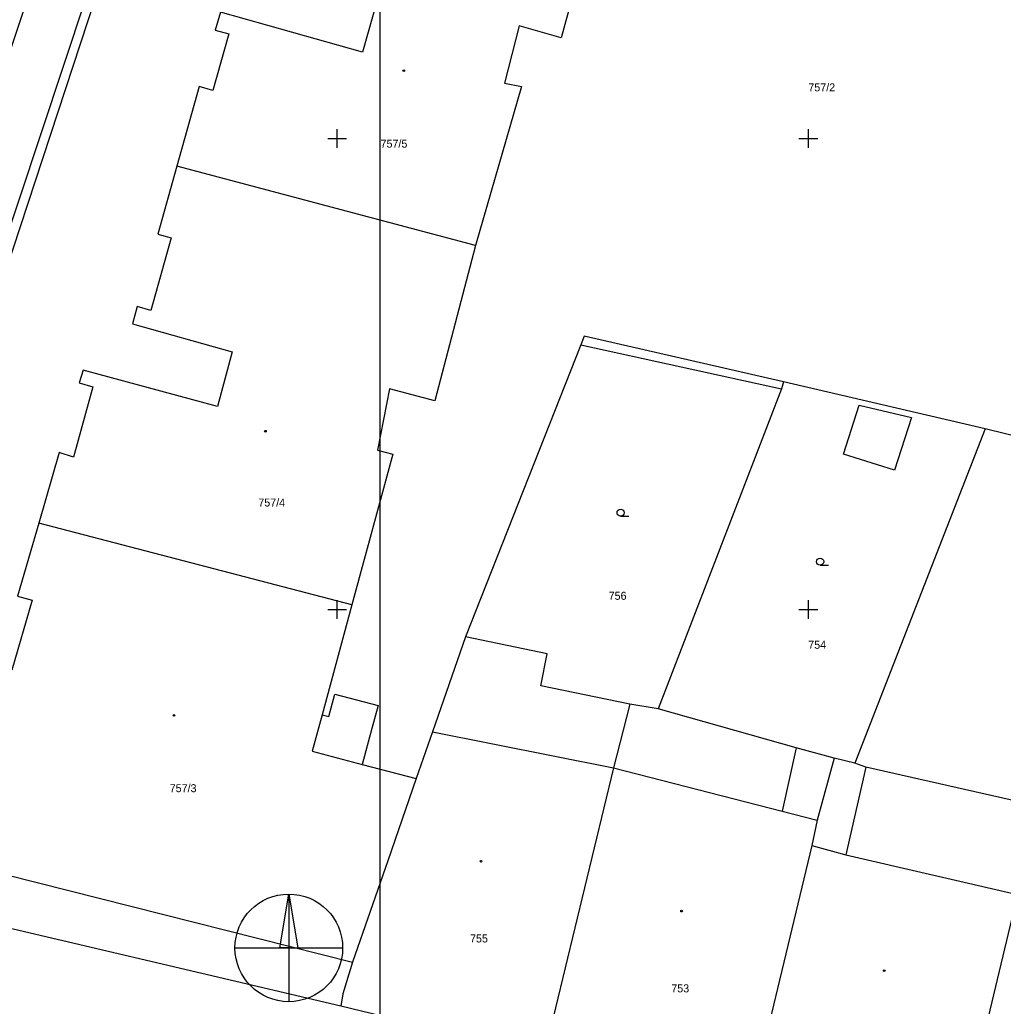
# Model space of a CAD drawing. Extents: x -599717 to -599336, y -1161826 to -1161587.
# Drawn here: x -599473.47 to -599431.73, y -1161736.85 to -1161694.96 of the extents above; entities that cross this region are included whole.
import ezdxf

# ---------------------------------------------------------------- set-up
doc = ezdxf.new("R2010")
doc.units = 0
for name, color, linetype in [('KN_Hranice parcel', 7, 'Continuous'), ('KN_Parcelní čísla', 7, 'Continuous'), ('KN_Vnitřní kresba', 7, 'Continuous'), ('KN_Značky budov', 7, 'Continuous'), ('KN_Značky kultur', 7, 'Continuous'), ('Vrstva 56', 7, 'Continuous'), ('X_RAM_ROZPISKA', 7, 'Continuous'), ('X_SOUR_KRIZKY_SEVER', 7, 'Continuous')]:
    doc.layers.add(name, color=color, linetype=linetype)

msp = doc.modelspace()

# ---------------------------------------------------------------- linework, layer by layer
at = {"layer": 'KN_Hranice parcel'}
for p, q in [((-599454.12, -1161704.55), (-599466.8, -1161701.17)), ((-599432.49, -1161712.33), (-599441.05, -1161710.34)), ((-599432.49, -1161712.33), (-599438.03, -1161726.53)), ((-599424.27, -1161714.38), (-599432.49, -1161712.33)), ((-599459.38, -1161719.8), (-599472.66, -1161716.33)), ((-599446.37, -1161724.22), (-599447.58, -1161724.02)), ((-599438.03, -1161726.53), (-599438.91, -1161726.32))]:
    msp.add_line(p, q, dxfattribs=at)
for points in [[(-599482.07, -1161728.43), (-599482.2, -1161727.17), (-599480.67, -1161718.88), (-599478.61, -1161710.51), (-599472.1, -1161690.95), (-599466.87, -1161675.9), (-599461.06, -1161668.48), (-599459.51, -1161667.19)], [(-599482.07, -1161728.43), (-599464.01, -1161674), (-599459.51, -1161667.19)], [(-599459.91, -1161683.02), (-599460.52, -1161682.87), (-599462.22, -1161689.15), (-599461.64, -1161689.31), (-599462.42, -1161692.2), (-599463, -1161692.05), (-599463.16, -1161692.62), (-599458.26, -1161693.97), (-599458.92, -1161696.33), (-599464.95, -1161694.63), (-599465.17, -1161695.4), (-599464.59, -1161695.56), (-599465.27, -1161697.96), (-599465.85, -1161697.8), (-599466.8, -1161701.17)], [(-599447.89, -1161686.25), (-599450.49, -1161695.73), (-599452.27, -1161695.22), (-599452.89, -1161697.65), (-599452.18, -1161697.79), (-599454.12, -1161704.55)], [(-599466.8, -1161701.17), (-599467.61, -1161704.06), (-599467.04, -1161704.22), (-599467.91, -1161707.3), (-599468.48, -1161707.14), (-599468.69, -1161707.87), (-599464.45, -1161709.06), (-599465.07, -1161711.38), (-599470.78, -1161709.84), (-599470.94, -1161710.37), (-599470.36, -1161710.54), (-599471.19, -1161713.54), (-599471.8, -1161713.33), (-599472.66, -1161716.33)], [(-599454.12, -1161704.55), (-599455.85, -1161711.14), (-599457.78, -1161710.63), (-599458.29, -1161713.23), (-599457.64, -1161713.4), (-599459.38, -1161719.8)], [(-599441.05, -1161710.34), (-599449.52, -1161708.39), (-599449.65, -1161708.76), (-599454.55, -1161721.16)], [(-599441.05, -1161710.34), (-599441.14, -1161710.63), (-599446.37, -1161724.22)], [(-599472.66, -1161716.33), (-599473.56, -1161719.43), (-599472.94, -1161719.61), (-599473.81, -1161722.58), (-599474.42, -1161722.4), (-599475.95, -1161727.69), (-599475.36, -1161727.86), (-599476.06, -1161730.26), (-599476.64, -1161730.09), (-599476.78, -1161730.57), (-599459.34, -1161734.98)], [(-599459.38, -1161719.8), (-599460.64, -1161724.48), (-599460.35, -1161724.55), (-599460.09, -1161723.59), (-599458.26, -1161724.08), (-599458.52, -1161725.05), (-599458.94, -1161726.58), (-599456.64, -1161727.18)], [(-599454.55, -1161721.16), (-599455.95, -1161725.2), (-599456.64, -1161727.18)], [(-599447.58, -1161724.02), (-599451.35, -1161723.24), (-599451.09, -1161721.88), (-599454.55, -1161721.16)], [(-599447.58, -1161724.02), (-599448.27, -1161726.72), (-599451.14, -1161738.62)], [(-599438.91, -1161726.32), (-599440.52, -1161725.88), (-599446.37, -1161724.22)], [(-599438.91, -1161726.32), (-599439.63, -1161728.95), (-599439.85, -1161730.03), (-599442.5, -1161741.05)], [(-599430.24, -1161728.35), (-599437.56, -1161726.69), (-599438.03, -1161726.53)], [(-599456.64, -1161727.18), (-599457.84, -1161730.67), (-599459.34, -1161734.98)], [(-599430.24, -1161728.35), (-599430.89, -1161731.22), (-599431.13, -1161732.11), (-599433.7, -1161742.87)], [(-599459.84, -1161736.84), (-599477.56, -1161732.68), (-599481.73, -1161731.59), (-599483.05, -1161731.39)], [(-599459.34, -1161734.98), (-599459.75, -1161736.32), (-599459.84, -1161736.84)], [(-599451.14, -1161738.62), (-599456.68, -1161737.34), (-599456.75, -1161737.6), (-599459.84, -1161736.84)]]:
    msp.add_lwpolyline(points, dxfattribs=at)
at = {"layer": 'KN_Vnitřní kresba'}
for p, q in [((-599464.97, -1161677.92), (-599478.91, -1161720.35)), ((-599449.65, -1161708.76), (-599441.14, -1161710.63)), ((-599438.51, -1161713.41), (-599437.84, -1161711.32)), ((-599437.84, -1161711.32), (-599435.62, -1161711.85)), ((-599435.62, -1161711.85), (-599436.35, -1161714.09)), ((-599436.35, -1161714.09), (-599438.51, -1161713.41)), ((-599460.64, -1161724.48), (-599461.06, -1161726.02)), ((-599455.95, -1161725.2), (-599448.27, -1161726.72)), ((-599461.06, -1161726.02), (-599458.94, -1161726.58)), ((-599440.52, -1161725.88), (-599441.11, -1161728.57)), ((-599448.27, -1161726.72), (-599441.11, -1161728.57)), ((-599437.56, -1161726.69), (-599438.41, -1161730.42)), ((-599441.11, -1161728.57), (-599439.63, -1161728.95)), ((-599439.85, -1161730.03), (-599438.41, -1161730.42)), ((-599438.41, -1161730.42), (-599431.13, -1161732.11))]:
    msp.add_line(p, q, dxfattribs=at)
at = {"layer": 'KN_Značky budov'}
for centre in [(-599457.171, -1161697.12), (-599463.041, -1161712.43), (-599466.921, -1161724.5), (-599453.891, -1161730.69), (-599445.381, -1161732.81), (-599436.781, -1161735.34)]:
    msp.add_circle(centre, 0.035, dxfattribs=at)
at = {"layer": 'KN_Značky kultur'}
for p, q in [((-599447.969, -1161716.04), (-599447.619, -1161716.04)), ((-599439.499, -1161718.12), (-599439.149, -1161718.12))]:
    msp.add_line(p, q, dxfattribs=at)
for centre in [(-599447.969, -1161715.89), (-599439.499, -1161717.97)]:
    msp.add_circle(centre, 0.15, dxfattribs=at)
at = {"layer": 'Vrstva 56'}
for p, q in [((-599462.05, -1161732.086), (-599461.669, -1161734.371)), ((-599464.335, -1161734.371), (-599459.765, -1161734.371)), ((-599462.05, -1161734.371), (-599462.05, -1161736.656))]:
    msp.add_line(p, q, dxfattribs=at)
msp.add_lwpolyline([(-599462.05, -1161732.086), (-599462.05, -1161734.371), (-599462.431, -1161734.371)], close=True, dxfattribs=at)
msp.add_circle((-599462.05, -1161734.371), 2.285, dxfattribs=at)
at = {"layer": 'X_RAM_ROZPISKA'}
msp.add_lwpolyline([(-599584.175, -1161747.535), (-599458.175, -1161747.535), (-599458.175, -1161628.735), (-599584.175, -1161628.735)], close=True, dxfattribs=at)
at = {"layer": 'X_SOUR_KRIZKY_SEVER'}
for p, q in [((-599460, -1161700.4), (-599460, -1161699.6)), ((-599440, -1161700.4), (-599440, -1161699.6)), ((-599460.4, -1161700), (-599459.6, -1161700)), ((-599440.4, -1161700), (-599439.6, -1161700)), ((-599460, -1161720.4), (-599460, -1161719.6)), ((-599440, -1161720.4), (-599440, -1161719.6)), ((-599460.4, -1161720), (-599459.6, -1161720)), ((-599440.4, -1161720), (-599439.6, -1161720))]:
    msp.add_line(p, q, dxfattribs=at)

# ---------------------------------------------------------------- texts
at = {"layer": 'KN_Parcelní čísla'}
for s, p in [('757/2', (-599440, -1161698)), ('757/5', (-599458.156, -1161700.39)), ('757/4', (-599463.343, -1161715.63)), ('756', (-599448.475, -1161719.59)), ('754', (-599440.005, -1161721.67)), ('757/3', (-599467.104, -1161727.76)), ('755', (-599454.358, -1161734.14)), ('753', (-599445.816, -1161736.26))]:
    msp.add_text(s, height=0.34, dxfattribs=at).set_placement(p)

doc.saveas('drawing.dxf')
